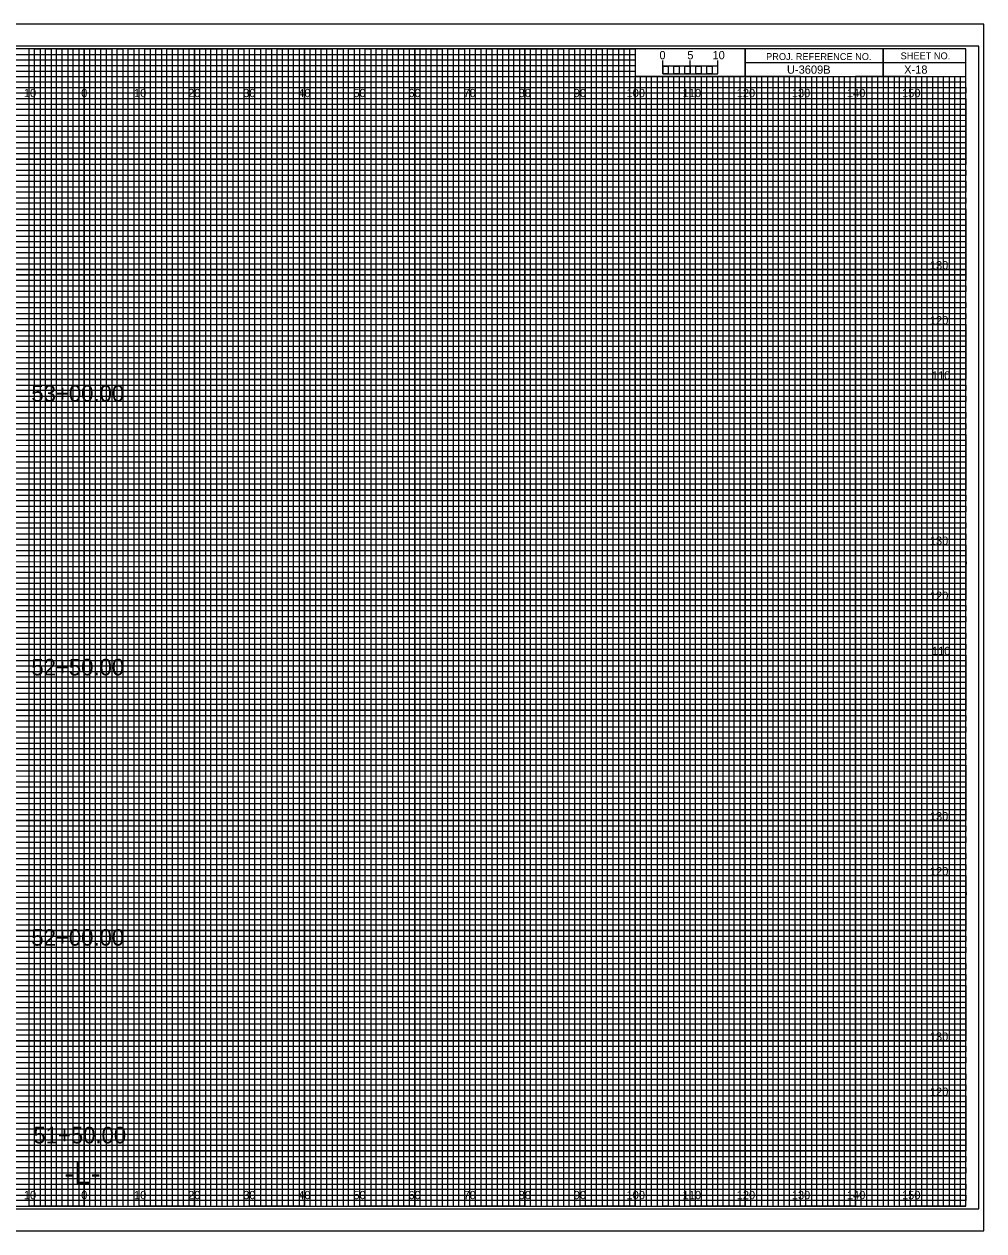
# Model space of a CAD drawing. Extents: x -13 to 329, y -17 to 10994.
# Drawn here: x 149.1 to 323.3, y 3515.5 to 3734.5 of the extents above; entities that cross this region are included whole.
import ezdxf

# ---------------------------------------------------------------- set-up
doc = ezdxf.new("R2010")
doc.units = 0
for name, color, linetype in [('Prop XS Alignment Label', 7, 'Continuous'), ('Prop XS Bar Scale Labels', 7, 'Continuous'), ('Prop XS Elevation Labels', 7, 'Continuous'), ('Prop XS Offset Labels', 7, 'Continuous'), ('Prop XS Project Number', 7, 'Continuous'), ('Prop XS Sheet Number', 7, 'Continuous'), ('Prop XS Station Labels', 7, 'Continuous'), ('Sheet Cross Section CELL', 7, 'Continuous'), ('Sheet Cross Section Grid Major CELL', 7, 'Continuous'), ('Sheet Cross Section Grid Middle CELL', 7, 'Continuous'), ('Sheet Cross Section Grid Minor 1 CELL', 7, 'Continuous'), ('Sheet Cross Section Grid Minor 2 CELL', 7, 'Continuous'), ('Sheet Cross Section Scale CELL', 7, 'Continuous'), ('Sheet Cutting Line CELL', 7, 'Continuous'), ('Sheet DOT Grid CELL', 7, 'Continuous'), ('Sheet Plot Border Inside CELL', 7, 'Continuous'), ('Sheet Plot Border Outside CELL', 7, 'Continuous')]:
    doc.layers.add(name, color=color, linetype=linetype)

msp = doc.modelspace()

# ---------------------------------------------------------------- linework, layer by layer
at = {"layer": 'Sheet Cross Section CELL'}
for p, q in [((305, 3730), (305, 3725)), ((305, 3725), (305, 3730)), ((280, 3727.5), (280, 3725)), ((320, 3727.49), (280, 3727.49)), ((280, 3725), (320, 3725))]:
    msp.add_line(p, q, dxfattribs=at)
for points in [[(320, 3730), (0, 3730), (0, 3520), (320, 3520)], [(280, 3730), (260, 3730), (260, 3725.03), (280, 3725.03)], [(320, 3730), (280, 3730), (280, 3725), (320, 3725)]]:
    msp.add_lwpolyline(points, close=True, dxfattribs=at)
at = {"layer": 'Sheet Cross Section Grid Major CELL'}
for p, q in [((150, 3730), (140, 3730)), ((150, 3520), (150, 3730)), ((170, 3730), (160, 3730)), ((160, 3730), (160, 3520)), ((170, 3520), (170, 3730)), ((190, 3730), (180, 3730)), ((180, 3730), (180, 3520)), ((190, 3520), (190, 3730)), ((210, 3730), (200, 3730)), ((200, 3730), (200, 3520)), ((210, 3520), (210, 3730)), ((230, 3730), (220, 3730)), ((220, 3730), (220, 3520)), ((230, 3520), (230, 3730)), ((250, 3730), (240, 3730)), ((240, 3730), (240, 3520)), ((250, 3520), (250, 3730)), ((260, 3730), (260, 3520)), ((270, 3520), (270, 3725)), ((290, 3725), (280, 3725)), ((280, 3725), (280, 3520)), ((290, 3520), (290, 3725)), ((310, 3725), (300, 3725)), ((300, 3725), (300, 3520)), ((310, 3520), (310, 3725)), ((160, 3520), (150, 3520)), ((180, 3520), (170, 3520)), ((200, 3520), (190, 3520)), ((220, 3520), (210, 3520)), ((240, 3520), (230, 3520)), ((260, 3520), (250, 3520)), ((280, 3520), (270, 3520)), ((300, 3520), (290, 3520)), ((320, 3520), (310, 3520)), ((320, 3520), (320, 3520))]:
    msp.add_line(p, q, dxfattribs=at)
for points in [[(0, 3720), (320, 3720), (320, 3710), (0, 3710)], [(0, 3700), (320, 3700), (320, 3690), (0, 3690)], [(0, 3680), (320, 3680), (320, 3670), (0, 3670)], [(0, 3660), (320, 3660), (320, 3650), (0, 3650)], [(0, 3640), (320, 3640), (320, 3630), (0, 3630)], [(0, 3620), (320, 3620), (320, 3610), (0, 3610)], [(0, 3600), (320, 3600), (320, 3590), (0, 3590)], [(0, 3580), (320, 3580), (320, 3570), (0, 3570)], [(0, 3560), (320, 3560), (320, 3550), (0, 3550)], [(0, 3540), (320, 3540), (320, 3530), (0, 3530)]]:
    msp.add_lwpolyline(points, dxfattribs=at)
at = {"layer": 'Sheet Cross Section Grid Middle CELL'}
for points in [[(145, 3520), (155, 3520), (155, 3730), (165, 3730), (165, 3520), (175, 3520), (175, 3730), (185, 3730), (185, 3520), (195, 3520), (195, 3730), (205, 3730), (205, 3520), (215, 3520), (215, 3730), (225, 3730), (225, 3520), (235, 3520), (235, 3730), (245, 3730), (245, 3520), (255, 3520), (255, 3730), (259.93, 3730), (260, 3730), (260, 3725), (264.99, 3725), (264.99, 3520), (275, 3520), (275, 3725), (285, 3725), (285, 3520), (295, 3520), (295, 3725), (305, 3725), (305, 3520), (315, 3520), (315, 3725)], [(0, 3725), (275, 3725)], [(0, 3705), (320, 3705), (320, 3715), (0, 3715)], [(0, 3685), (320, 3685), (320, 3695), (0, 3695)], [(0, 3665), (320, 3665), (320, 3675), (0, 3675)], [(0, 3645), (320, 3645), (320, 3655), (0, 3655)], [(0, 3625), (320, 3625), (320, 3635), (0, 3635)], [(0, 3605), (320, 3605), (320, 3615), (0, 3615)], [(0, 3585), (320, 3585), (320, 3595), (0, 3595)], [(0, 3565), (320, 3565), (320, 3575), (0, 3575)], [(0, 3545), (320, 3545), (320, 3555), (0, 3555)], [(0, 3525), (320, 3525), (320, 3535), (0, 3535)]]:
    msp.add_lwpolyline(points, dxfattribs=at)
at = {"layer": 'Sheet Cross Section Grid Minor 1 CELL'}
for p, q in [((0, 3729), (260, 3729)), ((260, 3727.98), (0, 3727.98)), ((260, 3729), (260, 3727.98)), ((0, 3727), (260, 3727)), ((260, 3725.89), (0, 3725.89)), ((260, 3727), (260, 3725.89)), ((0, 3724), (320, 3724))]:
    msp.add_line(p, q, dxfattribs=at)
for points in [[(0, 3723), (270, 3723), (320, 3723), (320, 3722), (0, 3722)], [(0, 3721), (320, 3721), (320, 3719), (0, 3719)], [(0, 3718), (320, 3718), (320, 3717), (0, 3716.98)], [(0, 3716), (320, 3716), (320, 3714), (0, 3714)], [(0, 3713), (320, 3713), (320, 3712), (0, 3712)], [(0, 3711), (320, 3711), (320, 3709), (0, 3709)], [(0, 3708), (320, 3708), (320, 3707), (0, 3707)], [(0, 3706), (320, 3706), (320, 3704), (0, 3704)], [(0, 3703), (320, 3703), (320, 3702), (0, 3702)], [(0, 3701), (320, 3701), (320, 3699), (0, 3699)], [(0, 3698), (320, 3698), (320, 3697), (0, 3697)], [(0, 3696), (320, 3696), (320, 3693.95), (320, 3693), (320, 3692), (0, 3692)], [(0, 3694), (320, 3694), (320, 3693), (0, 3693)], [(0, 3691), (320, 3691), (320, 3689), (0, 3689.03)], [(0, 3689.03), (320, 3689), (320, 3688), (0, 3688)], [(0, 3687), (320, 3687), (320, 3686), (0, 3686)], [(0, 3684), (320, 3684), (320, 3683), (0, 3683)], [(0, 3682), (320, 3682), (320, 3681), (0, 3681)], [(-0.07, 3678.89), (320, 3678.89), (320, 3677.88), (-0.07, 3677.88)], [(0, 3677), (320, 3677), (320, 3676), (0, 3676)], [(0, 3674), (320, 3674), (320, 3673), (0, 3673)], [(0, 3672), (320, 3672), (320, 3671), (0, 3671)], [(0, 3669), (320, 3669), (320, 3668), (0, 3668)], [(0, 3667), (320, 3667), (320, 3666), (0, 3666)], [(0, 3664), (320, 3664), (320, 3663), (0, 3663)], [(0, 3662), (320, 3662), (320, 3661), (0, 3661)], [(0, 3659), (320, 3659), (319.99, 3657.98), (0, 3658)], [(0, 3657), (320, 3657), (320, 3656), (0, 3656)], [(0, 3654), (320, 3654), (320, 3653), (0, 3653)], [(0, 3652), (320, 3652), (320, 3651), (0, 3651)], [(0, 3649), (320, 3649), (320, 3648), (0, 3648)], [(0, 3647), (320, 3647), (320, 3646), (0, 3646)], [(0, 3644), (320, 3644), (320, 3643), (0, 3643)], [(0, 3642), (320, 3642), (320, 3641), (0, 3641)], [(0, 3639), (320, 3639), (320, 3638), (0, 3638)], [(0, 3636.99), (320.07, 3636.91), (320, 3636), (0, 3636)], [(0, 3634), (320, 3634), (320, 3633), (0, 3633)], [(0, 3632), (320, 3632), (320, 3631), (0, 3631)], [(0, 3629), (320, 3629), (320, 3628), (0, 3628)], [(0, 3627), (320, 3627), (320, 3626), (0, 3626)], [(0, 3624), (320, 3624), (320, 3623), (0, 3623)], [(0, 3622), (320, 3622), (320, 3621), (0, 3621)], [(0, 3619), (320, 3619), (320, 3618), (0, 3618)], [(0, 3617), (320, 3617), (320, 3616), (0, 3616)], [(0, 3614), (320, 3614), (320, 3613), (0, 3613)], [(0, 3612), (320, 3612), (320, 3611), (0, 3611)], [(0, 3609), (320, 3609), (320, 3608), (0, 3608)], [(0, 3607), (320, 3607), (320, 3606), (0, 3606)], [(0, 3604), (320, 3604), (320, 3603), (0, 3603)], [(0, 3602), (320, 3602), (320, 3601), (0, 3601)], [(0, 3599), (320, 3599), (319.99, 3597.98), (0, 3598)], [(0, 3597), (320, 3597), (320, 3596), (0, 3596)], [(0, 3594), (320, 3594), (320, 3593), (0, 3593)], [(0, 3592), (320, 3592), (320, 3591), (0, 3591)], [(0, 3589), (320, 3589), (320, 3588), (0, 3588)], [(0, 3587), (320, 3587), (320, 3586), (0, 3586)], [(0, 3584), (320, 3584), (320, 3583), (0, 3583)], [(0, 3582), (320, 3582), (320, 3581), (0, 3581)], [(0, 3579), (320, 3579), (320, 3578), (0, 3578)], [(0, 3576.99), (320.07, 3576.91), (320, 3576), (0, 3576)], [(0, 3574), (320, 3574), (320, 3573), (0, 3573)], [(0, 3572), (320, 3572), (320, 3571), (0, 3571)], [(0, 3569), (320, 3569), (320, 3568), (0, 3568)], [(0, 3567), (320, 3567), (320, 3566), (0, 3566)], [(0, 3564), (320, 3564), (320, 3563), (0, 3563)], [(0, 3562), (320, 3562), (320, 3561), (0, 3561)], [(0, 3559), (320, 3559), (320, 3558), (0, 3558)], [(0, 3557), (320, 3557), (320, 3556), (0, 3556)], [(0, 3554), (320, 3554), (320, 3553), (0, 3553)], [(0, 3552), (320, 3552), (320, 3551), (0, 3551)], [(0, 3549), (320, 3549), (320, 3548), (0, 3548)], [(0, 3547), (320, 3547), (320, 3546), (0, 3546)], [(0, 3544), (320, 3544), (320, 3543), (0, 3543)], [(0, 3542), (320, 3542), (320, 3541), (0, 3541)], [(0, 3539), (320, 3539), (320, 3538), (0, 3538)], [(0, 3537), (320, 3537), (320, 3536), (0, 3536)], [(0, 3534), (320, 3534), (320, 3533), (0, 3533)], [(0, 3532), (320, 3532), (320, 3531), (0, 3531)], [(0, 3529), (320, 3529), (320, 3528), (0, 3528)], [(0, 3527), (320, 3527), (320, 3526), (0, 3526)], [(0, 3524), (320, 3524), (320, 3523), (0, 3523)], [(0, 3522), (320, 3522), (320, 3521), (0, 3521)]]:
    msp.add_lwpolyline(points, dxfattribs=at)
at = {"layer": 'Sheet Cross Section Grid Minor 2 CELL'}
for p, q in [((267, 3725), (266.01, 3725)), ((266.01, 3725), (266.01, 3520)), ((267, 3520), (267, 3725)), ((269, 3725), (268, 3725)), ((268, 3725), (268, 3520)), ((269, 3520), (269, 3725)), ((266.01, 3520), (265, 3520)), ((268, 3520), (267, 3520))]:
    msp.add_line(p, q, dxfattribs=at)
for points in [[(150, 3520), (151, 3520), (151, 3730), (152, 3730), (152, 3520)], [(152, 3520), (153, 3520), (153, 3730), (154, 3730), (154, 3520)], [(155, 3520), (156, 3520), (156, 3730), (157, 3730), (157, 3520)], [(157, 3520), (158, 3520), (158, 3730), (159, 3730), (159, 3520)], [(160, 3520), (161, 3520), (161, 3730), (162, 3730), (162, 3520)], [(162, 3520), (163, 3520), (163, 3730), (164, 3730), (164, 3520)], [(165, 3520), (166, 3520), (166, 3730), (167, 3730), (167, 3520)], [(167, 3520), (168, 3520), (168, 3730), (169, 3730), (169, 3520)], [(170, 3520), (171, 3520), (171, 3730), (172, 3730), (172, 3520)], [(172, 3520), (173, 3520), (173, 3730), (174, 3730), (174, 3520)], [(175, 3520), (176, 3520), (176, 3730), (177, 3730), (177, 3520)], [(177, 3520), (178, 3520), (178, 3730), (179, 3730), (179, 3520)], [(180, 3520), (181, 3520), (181, 3730), (182, 3730), (182, 3520)], [(182, 3520), (183, 3520), (183, 3730), (184, 3730), (184, 3520)], [(185, 3520), (186, 3520), (186, 3730), (187, 3730), (187, 3520)], [(187, 3520), (188, 3520), (188, 3730), (189, 3730), (189, 3520)], [(190, 3520), (191, 3520), (191, 3730), (192, 3730), (192, 3520)], [(192, 3520), (193, 3520), (193, 3730), (194, 3730), (194, 3520)], [(195, 3520), (196, 3520), (196, 3730), (197, 3730), (197, 3520)], [(197, 3520), (198, 3520), (198, 3730), (199, 3730), (199, 3520)], [(200, 3520), (201, 3520), (201, 3730), (202, 3730), (202, 3520)], [(202, 3520), (203, 3520), (203, 3730), (204, 3730), (204, 3520)], [(205, 3520), (206, 3520), (206, 3730), (207, 3730), (207, 3520)], [(207, 3520), (208, 3520), (208, 3730), (209, 3730), (209, 3520)], [(210, 3520), (211, 3520), (211, 3730), (212, 3730), (212, 3520)], [(212, 3520), (213, 3520), (213, 3730), (214, 3730), (214, 3520)], [(215, 3520), (216, 3520), (216, 3730), (217, 3730), (217, 3520)], [(217, 3520), (218, 3520), (218, 3730), (219, 3730), (219, 3520)], [(220, 3520), (221, 3520), (221, 3730), (222, 3730), (222, 3520)], [(222, 3520), (223, 3520), (223, 3730), (224, 3730), (224, 3520)], [(225, 3520), (226, 3520), (226, 3730), (227, 3730), (227, 3520)], [(227, 3520), (228, 3520), (228, 3730), (229, 3730), (229, 3520)], [(230, 3520), (231, 3520), (231, 3730), (232, 3730), (232, 3520)], [(232, 3520), (233, 3520), (233, 3730), (234, 3730), (234, 3520)], [(235, 3520), (236, 3520), (236, 3730), (237, 3730), (237, 3520)], [(237, 3520), (238, 3520), (238, 3730), (239, 3730), (239, 3520)], [(240, 3520), (241, 3520), (241, 3730), (242, 3730), (242, 3520)], [(242, 3520), (243, 3520), (243, 3730), (244, 3730), (244, 3520)], [(245, 3520), (246, 3520), (246, 3730), (247, 3730), (247, 3520)], [(247, 3520), (248, 3520), (248, 3730), (249, 3730), (249, 3520)], [(250, 3520), (251, 3520), (251, 3730), (252, 3730), (252, 3520)], [(252, 3520), (253, 3520), (253, 3730), (254, 3730), (254, 3520)], [(255, 3520), (256, 3520), (256, 3730), (257, 3730), (257, 3520)], [(257, 3520), (258, 3520), (258, 3730), (259, 3730), (259, 3520)], [(260, 3520), (261, 3520), (261, 3725), (262.02, 3725), (262.02, 3520)], [(262, 3520), (263, 3520), (263, 3725), (263.99, 3725), (263.99, 3520)], [(270, 3520), (270.98, 3520), (270.98, 3725), (272, 3725), (272, 3520)], [(272, 3520), (273, 3520), (273, 3725), (274.05, 3725), (274.05, 3520)], [(275, 3520), (276, 3520), (276, 3725), (277, 3725), (277, 3520)], [(277, 3520), (278, 3520), (278, 3725), (279, 3725), (279, 3520)], [(280, 3520), (281, 3520), (281, 3725), (282, 3725), (282, 3520)], [(282, 3520), (283, 3520), (283, 3725), (284, 3725), (284, 3520)], [(285, 3520), (286, 3520), (286, 3725), (287, 3725), (287, 3520)], [(287, 3520), (288, 3520), (288, 3725), (289, 3725), (289, 3520)], [(290, 3520), (291, 3520), (291, 3725), (292, 3725), (292, 3520)], [(292, 3520), (293, 3520), (293, 3725), (294, 3725), (294, 3520)], [(295, 3520), (296, 3520), (296, 3725), (297, 3725), (297, 3520)], [(297, 3520), (298, 3520), (298, 3725), (299, 3725), (299, 3520)], [(300, 3520), (301, 3520), (301, 3725), (302, 3725), (302, 3520)], [(302, 3520), (303, 3520), (303, 3725), (304, 3725), (304, 3520)], [(305, 3520), (306, 3520), (306, 3725), (307, 3725), (307, 3520)], [(307, 3520), (308, 3520), (308, 3725), (309, 3725), (309, 3520)], [(310, 3520), (311, 3520), (311, 3725), (312, 3725), (312, 3520)], [(312, 3520), (313, 3520), (313, 3725), (314, 3725), (314, 3520)], [(315, 3520), (316, 3520), (316, 3725), (317, 3725), (317, 3520)], [(317, 3520), (318, 3520), (318, 3725), (319, 3725), (319, 3520)]]:
    msp.add_lwpolyline(points, dxfattribs=at)
at = {"layer": 'Sheet Cross Section Scale CELL'}
for p, q in [((265, 3725.49), (265, 3727.9)), ((265, 3726.9), (265, 3727.9)), ((270, 3725.49), (270, 3727.9)), ((275, 3725.49), (275, 3727.9)), ((275, 3726.9), (275, 3727.9))]:
    msp.add_line(p, q, dxfattribs=at)
for points in [[(275, 3726.9), (265, 3726.9), (265, 3725.49), (275, 3725.49)], [(265, 3726.9), (266, 3726.9), (266, 3725.49), (265, 3725.49)], [(267, 3726.9), (268, 3726.9), (268, 3725.49), (267, 3725.49)], [(269, 3726.9), (270, 3726.9), (270, 3725.49), (269, 3725.49)], [(271, 3726.9), (272, 3726.9), (272, 3725.49), (271, 3725.49)], [(273, 3726.9), (274, 3726.9), (274, 3725.49), (273, 3725.49)]]:
    msp.add_lwpolyline(points, close=True, dxfattribs=at)
at = {"layer": 'Sheet Cutting Line CELL'}
for p, q in [((323.3, 3734.5), (-13.4, 3734.5)), ((-13.4, 3515.5), (323.3, 3515.5))]:
    msp.add_line(p, q, dxfattribs=at)
at = {"layer": 'Sheet DOT Grid CELL'}
for p, q in [((150, 3520), (150, 3730)), ((160, 3520), (160, 3730)), ((170, 3520), (170, 3730)), ((180, 3520), (180, 3730)), ((190, 3520), (190, 3730)), ((200, 3520), (200, 3730)), ((210, 3520), (210, 3730)), ((220, 3520), (220, 3730)), ((230, 3520), (230, 3730)), ((240, 3520), (240, 3730)), ((250, 3520), (250, 3730)), ((260, 3520), (260, 3724.69)), ((270, 3520), (270, 3724.69)), ((280, 3520), (280, 3724.69)), ((290, 3520), (290, 3724.69)), ((300, 3520), (300, 3724.69)), ((310, 3520), (310, 3724.69)), ((0, 3720), (320, 3720)), ((0, 3710), (320, 3710)), ((0, 3700), (320, 3700)), ((0, 3690), (320, 3690)), ((0, 3680), (320, 3680)), ((0, 3670), (320, 3670)), ((0, 3660), (320, 3660)), ((0, 3650), (320, 3650)), ((0, 3640), (320, 3640)), ((0, 3630), (320, 3630)), ((0, 3620), (320, 3620)), ((0, 3610), (320, 3610)), ((0, 3600), (320, 3600)), ((0, 3590), (320, 3590)), ((0, 3580), (320, 3580)), ((0, 3570), (320, 3570)), ((0, 3560), (320, 3560)), ((0, 3550), (320, 3550)), ((0, 3540), (320, 3540)), ((0, 3530), (320, 3530))]:
    msp.add_line(p, q, dxfattribs=at)
at = {"layer": 'Sheet Plot Border Inside CELL'}
msp.add_lwpolyline([(-10.8, 3519.5), (322.4, 3519.5), (322.4, 3730.5), (-10.8, 3730.5)], close=True, dxfattribs=at)
at = {"layer": 'Sheet Plot Border Outside CELL'}
msp.add_lwpolyline([(-13.4, 3515.5), (323.3, 3515.5), (323.3, 3734.5), (-13.4, 3734.5)], close=True, dxfattribs=at)

# ---------------------------------------------------------------- texts
at = {"layer": 'Prop XS Alignment Label'}
msp.add_text('-L-', height=4, dxfattribs=at).set_placement((156.42, 3524))
at = {"layer": 'Prop XS Bar Scale Labels'}
for s, p in [('5', (269.47, 3728.12)), ('10', (274.04, 3728.12))]:
    msp.add_text(s, height=1.5, dxfattribs=at).set_placement(p)
at = {"layer": 'Prop XS Elevation Labels'}
for s, p in [('130', (313.49, 3690)), ('120', (313.5, 3680)), ('110', (313.88, 3670)), ('130', (313.49, 3640)), ('120', (313.5, 3630)), ('110', (313.88, 3620)), ('130', (313.49, 3590)), ('120', (313.5, 3580)), ('130', (313.49, 3550)), ('120', (313.5, 3540))]:
    msp.add_text(s, height=1.5, dxfattribs=at).set_placement(p)
at = {"layer": 'Prop XS Offset Labels'}
for s, p in [('10', (149.04, 3721.25)), ('0', (159.45, 3721.25)), ('0', (159.45, 3721.25)), ('10', (169.04, 3721.25)), ('20', (178.86, 3721.25)), ('30', (188.86, 3721.25)), ('40', (198.86, 3721.25)), ('50', (208.86, 3721.25)), ('60', (218.86, 3721.25)), ('70', (228.86, 3721.25)), ('80', (238.86, 3721.25)), ('90', (248.86, 3721.25)), ('100', (258.44, 3721.25)), ('110', (268.62, 3721.25)), ('120', (278.44, 3721.25)), ('130', (288.44, 3721.25)), ('140', (298.44, 3721.25)), ('150', (308.44, 3721.25)), ('10', (149.04, 3521.25)), ('0', (159.45, 3521.25)), ('0', (159.45, 3521.25)), ('10', (169.04, 3521.25)), ('20', (178.86, 3521.25)), ('30', (188.86, 3521.25)), ('40', (198.86, 3521.25)), ('50', (208.86, 3521.25)), ('60', (218.86, 3521.25)), ('70', (228.86, 3521.25)), ('80', (238.86, 3521.25)), ('90', (248.86, 3521.25)), ('100', (258.44, 3521.25)), ('110', (268.62, 3521.25)), ('120', (278.44, 3521.25)), ('130', (288.44, 3521.25)), ('140', (298.44, 3521.25)), ('150', (308.44, 3521.25))]:
    msp.add_text(s, height=1.5, dxfattribs=at).set_placement(p)
at = {"layer": 'Prop XS Project Number'}
msp.add_text('U-3609B', height=1.5, dxfattribs=at).set_placement((287.56, 3725.5))
at = {"layer": 'Prop XS Sheet Number'}
msp.add_text('X-18', height=1.5, dxfattribs=at).set_placement((308.83, 3725.5))
at = {"layer": 'Prop XS Station Labels'}
for s, p in [('53+00.00', (150.41, 3665.99)), ('52+50.00', (150.41, 3616.31)), ('52+00.00', (150.41, 3567.26)), ('51+50.00', (150.77, 3531.38))]:
    msp.add_text(s, height=3, dxfattribs=at).set_placement(p)
at = {"layer": 'Sheet Cross Section CELL'}
for s, p in [('PROJ. REFERENCE NO.', (283.77, 3727.99)), ('SHEET NO.', (308.19, 3728.12))]:
    msp.add_text(s, height=1.25, dxfattribs=at).set_placement(p)
at = {"layer": 'Sheet Cross Section Scale CELL'}
msp.add_text('0', height=1.5, dxfattribs=at).set_placement((264.41, 3728.12))

doc.saveas('drawing.dxf')
